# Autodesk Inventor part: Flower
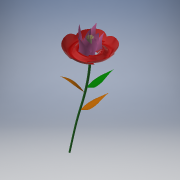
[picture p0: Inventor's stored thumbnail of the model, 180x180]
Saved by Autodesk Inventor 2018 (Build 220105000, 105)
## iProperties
Created: 2006-10
Document SubType Name: Modeling
Designer: Autodesk, Inc.
Density: 1 g/cm^3
Material: Generic
Appearance: Default
Author: Autodesk, Inc.
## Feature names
1. Circular Pattern2
2. Rectangular Pattern1
## Parameters: d0 = 63.5 mm, d3 = 0, d9 = 0, d10 = 0, d11 = 2.02683 mm, d13 = 63.5 mm, d15 = 42.60584 mm, d17 = 0, d18 = 90 deg, d19 = 90 deg, d24 = 47.625 mm, d25 = 7.5 mm, d26 = 16.129 mm, d27 = 5.84866 mm, d28 = 5.08 mm, d31 = 0, d32 = 90 deg, d33 = 76.2 mm, d34 = 5 mm, d35 = 12.7 mm, d36 = 15 deg, d46 = 0, d47 = 90 deg, d48 = 0, d49 = 90 deg, d50 = 0, d51 = 90 deg, d53 = 360 deg, d55 = 25.4 mm, d56 = 2.5 mm, d57 = 25.4 mm, d58 = 20 deg, d59 = 88.9 mm, d60 = 36 deg, d61 = 0, d62 = 90 deg, d63 = 0, d64 = 90 deg, d65 = 0, d66 = 90 deg, d67 = 38.1 mm, d68 = 2.5 mm, d69 = 38.1 mm, d70 = 20 deg, d71 = 0, d72 = 76.2 mm, d73 = 0, d74 = 0.254 mm, d75 = 0, d76 = 3.81 mm, d79 = 38.1 mm, d80 = 5.08 mm, d81 = 5.08 mm, d82 = 6.35 mm, d83 = 0, d84 = 90 deg, d85 = 33.02 mm, d86 = 12.7 mm, d88 = -0.03491 mm, d89 = 0, d90 = 90 deg, d91 = 0, d92 = 90 deg, d93 = 0, d94 = 90 deg, d95 = 0, d96 = 90 deg, d97 = 38.1 mm, d100 = 81.28 mm, d101 = 0, d102 = 90 deg, d103 = 0, d104 = 90 deg, d105 = 0, d106 = 90 deg, d107 = 0, d108 = 90 deg, d109 = 50.8 mm, d110 = 0, d111 = 0, d112 = 0
